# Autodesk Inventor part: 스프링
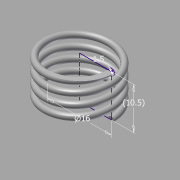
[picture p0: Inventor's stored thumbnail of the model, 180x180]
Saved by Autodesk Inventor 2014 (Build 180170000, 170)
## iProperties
Created: 2015-07
Part Number: 스프링
Material: 강철, 연강
Document SubType Name: Modeling
Designer: Administrator
Density: 7.86 g/cm^3
Appearance: 강철
Mass: 2.70836 g
Surface Area: 9.40557 cm^2
Volume: 0.344575 cm^3
Author: Administrator
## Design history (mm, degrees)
sketch "스케치1"
  geometry: L1 (0, 0)-(-8, 0); L2 (-8, 0)-(-8, -10.5); L3 (-8, -10.5)-(0, -10.5); L4 (0, -10.5)-(0, 0); C1 r 0.75 at (-8, 0)
  constraints: 8 end point, 2 parallel, 1 centre point, 1 coincident, 1 horizontal, 1 perpendicular
  dimensions: "d0" = 16 diameter of L2 L4; "d1" = 10.5 distance of L1.end L2.end (derived); "d2" = 1.5 diameter of C1
feature "코일1" pitch "d3" = 10; turns "d5" = 4; dims "d4" = 10.5 (= d1), "d6" = 0, angle "d7" = 90 deg, angle "d8" = 90 deg, "d9" = 0, "d10" = 0
sketch "스케치2"
  geometry: L1 (7.25, 0)-(8.75, 0) reference; 1 further point
  constraints: 1 horizontal alignment
extrude "돌출1" cut sketch "스케치2" stored distance "d11" = 10; taper "d12" = 0 deg
node "작업 평면1"
sketch "스케치3"
  geometry: L1 (8.75, 0)-(7.25, 0) reference; 1 further point
  constraints: 1 horizontal alignment
extrude "돌출2" cut sketch "스케치3" stored distance "d13" = 10; taper "d14" = 0 deg
node "솔리드1"
node "절단 모서리 투영1"
node "절단 모서리 투영2"
